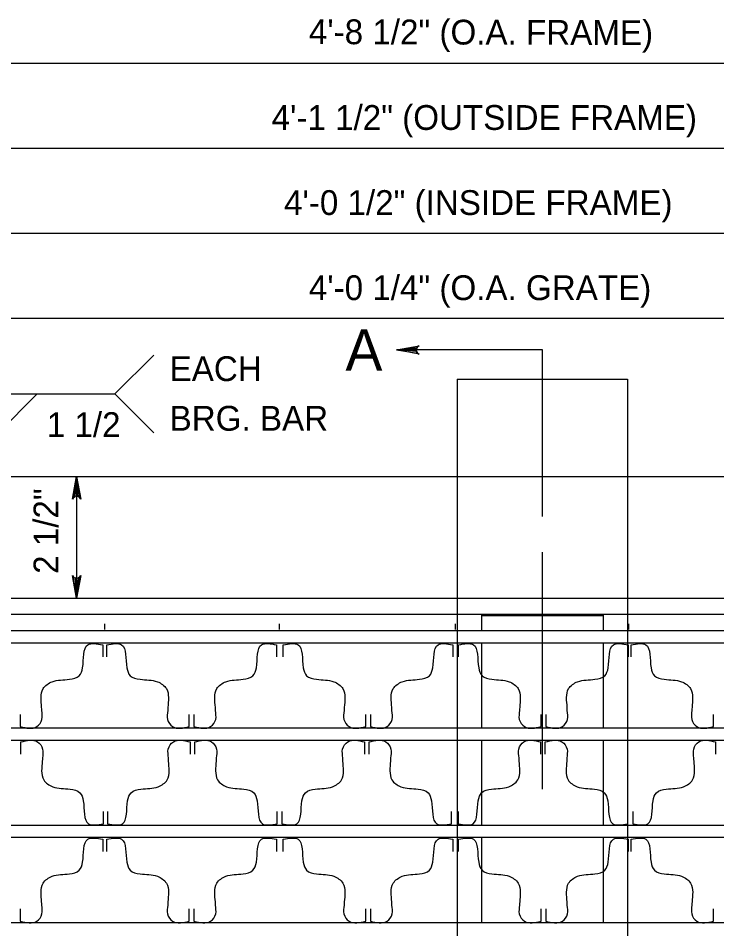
# Model space of a CAD drawing. Extents: x 0.71 to 8.05, y -5.67 to 4.31.
# Drawn here: x 3.343 to 5.033, y 2.109 to 4.312 of the extents above; entities that cross this region are included whole.
import ezdxf

# ---------------------------------------------------------------- set-up
doc = ezdxf.new("R2010")
doc.units = 0
for name, color, linetype in [('DETL-DIMS', 7, 'Continuous'), ('DETL-LINE', 7, 'Continuous'), ('DETL-NOTE', 7, 'Continuous'), ('DETL-TITL', 7, 'Continuous')]:
    doc.layers.add(name, color=color, linetype=linetype)

msp = doc.modelspace()

# ---------------------------------------------------------------- linework, layer by layer
at = {"layer": 'DETL-DIMS'}
for p, q in [((2.1992, 4.2036), (7.0228, 4.2036)), ((2.5328, 3.9977), (6.6892, 3.9977)), ((2.5722, 3.7918), (6.6498, 3.7918)), ((2.6116, 3.586), (6.6104, 3.586)), ((4.611, 3.5095), (4.2581, 3.5095)), ((4.611, 3.1067), (4.611, 3.5095)), ((3.4841, 3.2036), (3.4841, 2.9095)), ((4.611, 2.4472), (4.611, 3.0207))]:
    msp.add_line(p, q, dxfattribs=at)
for points in [[(4.2581, 3.5095), (4.3129, 3.5198), (4.3087, 3.5168), (4.3065, 3.5132), (4.3058, 3.5095), (4.3065, 3.5058), (4.3087, 3.5021), (4.3129, 3.4992), (4.2581, 3.5095), (4.3087, 3.5021), (4.3065, 3.5058), (4.2581, 3.5095), (4.3058, 3.5095), (4.3065, 3.5132), (4.2581, 3.5095), (4.3087, 3.5168)], [(3.671, 3.4972), (3.5769, 3.403), (3.671, 3.3089)], [(3.1063, 3.403), (3.3886, 3.403), (3.2945, 3.3089), (3.2945, 3.403), (3.5769, 3.403)], [(3.4841, 3.2036), (3.4944, 3.1488), (3.4914, 3.153), (3.4878, 3.1552), (3.4841, 3.1558), (3.4804, 3.1552), (3.4767, 3.153), (3.4738, 3.1488), (3.4841, 3.2036), (3.4767, 3.153), (3.4804, 3.1552), (3.4841, 3.2036), (3.4841, 3.1558), (3.4878, 3.1552), (3.4841, 3.2036), (3.4914, 3.153)], [(3.4841, 2.9095), (3.4738, 2.9643), (3.4767, 2.9601), (3.4804, 2.9579), (3.4841, 2.9573), (3.4878, 2.9579), (3.4914, 2.9601), (3.4944, 2.9643), (3.4841, 2.9095), (3.4914, 2.9601), (3.4878, 2.9579), (3.4841, 2.9095), (3.4841, 2.9573), (3.4804, 2.9579), (3.4841, 2.9095), (3.4767, 2.9601)]]:
    msp.add_lwpolyline(points, dxfattribs=at)
at = {"layer": 'DETL-LINE'}
for p, q in [((4.4051, 3.4389), (4.4051, 0.3107)), ((4.4051, 3.4389), (4.8169, 3.4389)), ((4.8169, 3.4389), (4.8169, 0.3107)), ((2.1992, 3.2036), (7.0228, 3.2036)), ((2.1992, 2.9095), (7.0228, 2.9095)), ((2.1992, 2.8701), (7.0228, 2.8701)), ((4.4639, 2.8701), (4.4639, 2.8307)), ((4.4639, 2.8672), (4.7581, 2.8672)), ((4.7581, 2.8701), (4.7581, 2.8307)), ((3.5527, 2.8331), (3.5527, 2.8468)), ((3.9753, 2.8331), (3.9753, 2.8468)), ((4.4009, 2.8331), (4.4009, 2.8468)), ((4.8205, 2.8331), (4.8205, 2.8468)), ((2.6116, 2.8307), (6.6104, 2.8307)), ((2.651, 2.8013), (6.571, 2.8013)), ((4.4639, 2.8013), (4.4639, 2.5954)), ((4.7581, 2.8013), (4.7581, 2.5954)), ((3.5473, 2.7965), (3.5473, 2.7671)), ((3.5572, 2.7671), (3.5572, 2.7965)), ((3.9676, 2.7965), (3.9676, 2.7671)), ((3.984, 2.7671), (3.984, 2.7965)), ((4.3944, 2.7965), (4.3944, 2.7671)), ((4.4083, 2.7671), (4.4083, 2.7965)), ((4.8187, 2.7965), (4.8187, 2.7671)), ((4.8255, 2.7671), (4.8255, 2.7965)), ((3.3477, 2.6279), (3.3477, 2.5984)), ((3.7568, 2.5984), (3.7568, 2.6279)), ((3.768, 2.6279), (3.768, 2.5984)), ((4.1836, 2.5984), (4.1836, 2.6279)), ((4.1948, 2.6279), (4.1948, 2.5984)), ((4.6079, 2.5984), (4.6079, 2.6279)), ((4.6191, 2.6279), (4.6191, 2.5984)), ((5.025, 2.5984), (5.025, 2.6279)), ((2.651, 2.5954), (6.571, 2.5954)), ((2.651, 2.566), (6.571, 2.566)), ((3.3492, 2.5321), (3.3492, 2.5615)), ((3.7586, 2.5615), (3.7586, 2.5321)), ((3.7699, 2.5321), (3.7699, 2.5615)), ((4.1804, 2.5615), (4.1804, 2.5321)), ((4.1917, 2.5321), (4.1917, 2.5615)), ((4.4639, 2.566), (4.4639, 2.3601)), ((4.6068, 2.5615), (4.6068, 2.5321)), ((4.6181, 2.5321), (4.6181, 2.5615)), ((4.7581, 2.566), (4.7581, 2.3601)), ((5.0298, 2.5615), (5.0298, 2.5321)), ((3.5488, 2.3634), (3.5488, 2.3929)), ((3.5591, 2.3929), (3.5591, 2.3634)), ((3.9694, 2.3634), (3.9694, 2.3929)), ((3.9809, 2.3929), (3.9809, 2.3634)), ((4.3912, 2.3634), (4.3912, 2.3929)), ((4.4073, 2.3929), (4.4073, 2.3634)), ((4.8176, 2.3634), (4.8176, 2.3929)), ((4.8302, 2.3929), (4.8302, 2.3634)), ((2.651, 2.3601), (6.571, 2.3601)), ((2.651, 2.3307), (6.571, 2.3307)), ((3.5473, 2.3259), (3.5473, 2.2965)), ((3.5572, 2.2965), (3.5572, 2.3259)), ((3.9676, 2.3259), (3.9676, 2.2965)), ((3.984, 2.2965), (3.984, 2.3259)), ((4.3944, 2.3259), (4.3944, 2.2965)), ((4.4083, 2.2965), (4.4083, 2.3259)), ((4.4639, 2.3307), (4.4639, 2.1248)), ((4.7581, 2.3307), (4.7581, 2.1248)), ((4.8187, 2.3259), (4.8187, 2.2965)), ((4.8255, 2.2965), (4.8255, 2.3259)), ((3.3477, 2.1573), (3.3477, 2.1279)), ((3.7568, 2.1279), (3.7568, 2.1573)), ((3.768, 2.1573), (3.768, 2.1279)), ((4.1836, 2.1279), (4.1836, 2.1573)), ((4.1948, 2.1573), (4.1948, 2.1279)), ((4.6079, 2.1279), (4.6079, 2.1573)), ((4.6191, 2.1573), (4.6191, 2.1279)), ((5.025, 2.1279), (5.025, 2.1573)), ((2.651, 2.1248), (6.571, 2.1248))]:
    msp.add_line(p, q, dxfattribs=at)
for points in [[(3.3477, 2.5984), (3.3881, 2.5985), (3.4004, 2.6158), (3.4, 2.6372), (3.3995, 2.6449), (3.4031, 2.6903), (3.425, 2.707), (3.4667, 2.7129), (3.4906, 2.7216), (3.4987, 2.7409), (3.5113, 2.7965), (3.5473, 2.7965)], [(3.5572, 2.7965), (3.5931, 2.7965), (3.6057, 2.7409), (3.6139, 2.7216), (3.6377, 2.7129), (3.6795, 2.707), (3.7014, 2.6903), (3.7049, 2.6449), (3.7045, 2.6372), (3.704, 2.6158), (3.7164, 2.5985), (3.7568, 2.5984)], [(3.768, 2.5984), (3.8084, 2.5985), (3.8207, 2.6158), (3.8203, 2.6372), (3.8198, 2.6449), (3.8234, 2.6903), (3.8453, 2.707), (3.887, 2.7129), (3.9108, 2.7216), (3.919, 2.7409), (3.9316, 2.7965), (3.9676, 2.7965)], [(3.984, 2.7965), (4.02, 2.7965), (4.0326, 2.7409), (4.0407, 2.7216), (4.0646, 2.7129), (4.1063, 2.707), (4.1282, 2.6903), (4.1318, 2.6449), (4.1313, 2.6372), (4.1309, 2.6158), (4.1432, 2.5985), (4.1836, 2.5984)], [(4.1948, 2.5984), (4.2352, 2.5985), (4.2476, 2.6158), (4.2471, 2.6372), (4.2467, 2.6449), (4.2502, 2.6903), (4.2721, 2.707), (4.3139, 2.7129), (4.3377, 2.7216), (4.3459, 2.7409), (4.3585, 2.7965), (4.3944, 2.7965)], [(4.4083, 2.7965), (4.4443, 2.7965), (4.4569, 2.7409), (4.4651, 2.7216), (4.4889, 2.7129), (4.5306, 2.707), (4.5525, 2.6903), (4.5561, 2.6449), (4.5556, 2.6372), (4.5552, 2.6158), (4.5675, 2.5985), (4.6079, 2.5984)], [(4.6191, 2.5984), (4.6595, 2.5985), (4.6719, 2.6158), (4.6714, 2.6372), (4.671, 2.6449), (4.6745, 2.6903), (4.6964, 2.707), (4.7382, 2.7129), (4.762, 2.7216), (4.7702, 2.7409), (4.7828, 2.7965), (4.8187, 2.7965)], [(4.6191, 2.5984), (4.6595, 2.5985), (4.6719, 2.6158), (4.6714, 2.6372), (4.671, 2.6449), (4.6745, 2.6903), (4.6964, 2.707), (4.7382, 2.7129), (4.762, 2.7216), (4.7702, 2.7409), (4.7828, 2.7965), (4.8187, 2.7965)], [(4.8255, 2.7965), (4.8614, 2.7965), (4.874, 2.7409), (4.8822, 2.7216), (4.906, 2.7129), (4.9478, 2.707), (4.9696, 2.6903), (4.9732, 2.6449), (4.9727, 2.6372), (4.9723, 2.6158), (4.9847, 2.5985), (5.025, 2.5984)], [(4.8255, 2.7965), (4.8614, 2.7965), (4.874, 2.7409), (4.8822, 2.7216), (4.906, 2.7129), (4.9478, 2.707), (4.9696, 2.6903), (4.9732, 2.6449), (4.9727, 2.6372), (4.9723, 2.6158), (4.9847, 2.5985), (5.025, 2.5984)], [(3.3492, 2.5615), (3.3896, 2.5615), (3.4019, 2.5442), (3.4015, 2.5227), (3.401, 2.515), (3.4046, 2.4696), (3.4265, 2.4529), (3.4683, 2.4471), (3.4921, 2.4384), (3.5002, 2.4191), (3.5128, 2.3634), (3.5488, 2.3634)], [(3.5591, 2.3634), (3.595, 2.3634), (3.6076, 2.4191), (3.6158, 2.4384), (3.6396, 2.4471), (3.6814, 2.4529), (3.7032, 2.4696), (3.7068, 2.515), (3.7064, 2.5227), (3.7059, 2.5442), (3.7183, 2.5615), (3.7586, 2.5615)], [(3.7699, 2.5615), (3.8102, 2.5615), (3.8226, 2.5442), (3.8221, 2.5227), (3.8217, 2.515), (3.8253, 2.4696), (3.8471, 2.4529), (3.8889, 2.4471), (3.9127, 2.4384), (3.9209, 2.4191), (3.9335, 2.3634), (3.9694, 2.3634)], [(3.9809, 2.3634), (4.0168, 2.3634), (4.0294, 2.4191), (4.0376, 2.4384), (4.0614, 2.4471), (4.1032, 2.4529), (4.125, 2.4696), (4.1286, 2.515), (4.1282, 2.5227), (4.1277, 2.5442), (4.1401, 2.5615), (4.1804, 2.5615)], [(4.1917, 2.5615), (4.232, 2.5615), (4.2444, 2.5442), (4.2439, 2.5227), (4.2435, 2.515), (4.2471, 2.4696), (4.2689, 2.4529), (4.3107, 2.4471), (4.3345, 2.4384), (4.3427, 2.4191), (4.3553, 2.3634), (4.3912, 2.3634)], [(4.4073, 2.3634), (4.4432, 2.3634), (4.4558, 2.4191), (4.464, 2.4384), (4.4878, 2.4471), (4.5296, 2.4529), (4.5514, 2.4696), (4.555, 2.515), (4.5546, 2.5227), (4.5541, 2.5442), (4.5665, 2.5615), (4.6068, 2.5615)], [(4.6181, 2.5615), (4.6584, 2.5615), (4.6708, 2.5442), (4.6703, 2.5227), (4.6699, 2.515), (4.6735, 2.4696), (4.6953, 2.4529), (4.7371, 2.4471), (4.7609, 2.4384), (4.7691, 2.4191), (4.7817, 2.3634), (4.8176, 2.3634)], [(4.8302, 2.3634), (4.8662, 2.3634), (4.8788, 2.4191), (4.8869, 2.4384), (4.9107, 2.4471), (4.9525, 2.4529), (4.9744, 2.4696), (4.9779, 2.515), (4.9775, 2.5227), (4.9771, 2.5442), (4.9894, 2.5615), (5.0298, 2.5615)], [(3.3477, 2.1279), (3.3881, 2.1279), (3.4004, 2.1452), (3.4, 2.1666), (3.3995, 2.1743), (3.4031, 2.2198), (3.425, 2.2364), (3.4667, 2.2423), (3.4906, 2.251), (3.4987, 2.2703), (3.5113, 2.326), (3.5473, 2.3259)], [(3.3477, 2.1279), (3.3881, 2.1279), (3.4004, 2.1452), (3.4, 2.1666), (3.3995, 2.1743), (3.4031, 2.2198), (3.425, 2.2364), (3.4667, 2.2423), (3.4906, 2.251), (3.4987, 2.2703), (3.5113, 2.326), (3.5473, 2.3259)], [(3.3477, 2.1279), (3.3881, 2.1279), (3.4004, 2.1452), (3.4, 2.1666), (3.3995, 2.1743), (3.4031, 2.2198), (3.425, 2.2364), (3.4667, 2.2423), (3.4906, 2.251), (3.4987, 2.2703), (3.5113, 2.326), (3.5473, 2.3259)], [(3.5572, 2.3259), (3.5931, 2.326), (3.6057, 2.2703), (3.6139, 2.251), (3.6377, 2.2423), (3.6795, 2.2364), (3.7014, 2.2198), (3.7049, 2.1743), (3.7045, 2.1666), (3.704, 2.1452), (3.7164, 2.1279), (3.7568, 2.1279)], [(3.5572, 2.3259), (3.5931, 2.326), (3.6057, 2.2703), (3.6139, 2.251), (3.6377, 2.2423), (3.6795, 2.2364), (3.7014, 2.2198), (3.7049, 2.1743), (3.7045, 2.1666), (3.704, 2.1452), (3.7164, 2.1279), (3.7568, 2.1279)], [(3.768, 2.1279), (3.8084, 2.1279), (3.8207, 2.1452), (3.8203, 2.1666), (3.8198, 2.1743), (3.8234, 2.2198), (3.8453, 2.2364), (3.887, 2.2423), (3.9108, 2.251), (3.919, 2.2703), (3.9316, 2.326), (3.9676, 2.3259)], [(3.768, 2.1279), (3.8084, 2.1279), (3.8207, 2.1452), (3.8203, 2.1666), (3.8198, 2.1743), (3.8234, 2.2198), (3.8453, 2.2364), (3.887, 2.2423), (3.9108, 2.251), (3.919, 2.2703), (3.9316, 2.326), (3.9676, 2.3259)], [(3.984, 2.3259), (4.02, 2.326), (4.0326, 2.2703), (4.0407, 2.251), (4.0646, 2.2423), (4.1063, 2.2364), (4.1282, 2.2198), (4.1318, 2.1743), (4.1313, 2.1666), (4.1309, 2.1452), (4.1432, 2.1279), (4.1836, 2.1279)], [(3.984, 2.3259), (4.02, 2.326), (4.0326, 2.2703), (4.0407, 2.251), (4.0646, 2.2423), (4.1063, 2.2364), (4.1282, 2.2198), (4.1318, 2.1743), (4.1313, 2.1666), (4.1309, 2.1452), (4.1432, 2.1279), (4.1836, 2.1279)], [(4.1948, 2.1279), (4.2352, 2.1279), (4.2476, 2.1452), (4.2471, 2.1666), (4.2467, 2.1743), (4.2502, 2.2198), (4.2721, 2.2364), (4.3139, 2.2423), (4.3377, 2.251), (4.3459, 2.2703), (4.3585, 2.326), (4.3944, 2.3259)], [(4.1948, 2.1279), (4.2352, 2.1279), (4.2476, 2.1452), (4.2471, 2.1666), (4.2467, 2.1743), (4.2502, 2.2198), (4.2721, 2.2364), (4.3139, 2.2423), (4.3377, 2.251), (4.3459, 2.2703), (4.3585, 2.326), (4.3944, 2.3259)], [(4.4083, 2.3259), (4.4443, 2.326), (4.4569, 2.2703), (4.4651, 2.251), (4.4889, 2.2423), (4.5306, 2.2364), (4.5525, 2.2198), (4.5561, 2.1743), (4.5556, 2.1666), (4.5552, 2.1452), (4.5675, 2.1279), (4.6079, 2.1279)], [(4.4083, 2.3259), (4.4443, 2.326), (4.4569, 2.2703), (4.4651, 2.251), (4.4889, 2.2423), (4.5306, 2.2364), (4.5525, 2.2198), (4.5561, 2.1743), (4.5556, 2.1666), (4.5552, 2.1452), (4.5675, 2.1279), (4.6079, 2.1279)], [(4.6191, 2.1279), (4.6595, 2.1279), (4.6719, 2.1452), (4.6714, 2.1666), (4.671, 2.1743), (4.6745, 2.2198), (4.6964, 2.2364), (4.7382, 2.2423), (4.762, 2.251), (4.7702, 2.2703), (4.7828, 2.326), (4.8187, 2.3259)], [(4.6191, 2.1279), (4.6595, 2.1279), (4.6719, 2.1452), (4.6714, 2.1666), (4.671, 2.1743), (4.6745, 2.2198), (4.6964, 2.2364), (4.7382, 2.2423), (4.762, 2.251), (4.7702, 2.2703), (4.7828, 2.326), (4.8187, 2.3259)], [(4.8255, 2.3259), (4.8614, 2.326), (4.874, 2.2703), (4.8822, 2.251), (4.906, 2.2423), (4.9478, 2.2364), (4.9696, 2.2198), (4.9732, 2.1743), (4.9727, 2.1666), (4.9723, 2.1452), (4.9847, 2.1279), (5.025, 2.1279)], [(4.8255, 2.3259), (4.8614, 2.326), (4.874, 2.2703), (4.8822, 2.251), (4.906, 2.2423), (4.9478, 2.2364), (4.9696, 2.2198), (4.9732, 2.1743), (4.9727, 2.1666), (4.9723, 2.1452), (4.9847, 2.1279), (5.025, 2.1279)]]:
    msp.add_spline(points, degree=3, dxfattribs=at)

# ---------------------------------------------------------------- texts
at = {"layer": 'DETL-NOTE'}
for s, rotation, p in [('4\'-8 1/2" (O.A. FRAME)', 359.8328, (4.046, 4.2494)), ('2 1/2"', 90, (3.44, 2.9678))]:
    msp.add_text(s, height=0.06, rotation=rotation, dxfattribs=at).set_placement(p)
for s, p in [('4\'-1 1/2" (OUTSIDE FRAME)', (3.956, 4.0418)), ('4\'-0 1/2" (INSIDE FRAME)', (3.986, 3.836)), ('4\'-0 1/4" (O.A. GRATE)', (4.046, 3.6301)), ('EACH', (3.7092, 3.4342)), ('BRG. BAR', (3.7092, 3.3142)), ('1 1/2', (3.412, 3.2989))]:
    msp.add_text(s, height=0.06, dxfattribs=at).set_placement(p)
at = {"layer": 'DETL-TITL'}
msp.add_text('A', height=0.1, dxfattribs=at).set_placement((4.1347, 3.4595))

doc.saveas('drawing.dxf')
